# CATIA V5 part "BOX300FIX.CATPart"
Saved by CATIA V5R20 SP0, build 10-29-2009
Part number: BOX300FIX
Bounding box of the stored display mesh (mm): x 0 to 476, y -20 to 55, z -40 to 15
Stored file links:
  C:\Users\Utente\Desktop\IO LAVORO\3D X SITO CF\X SITO\PLASTICA\BOX\BOX300FIX.CATPart
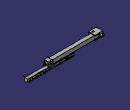
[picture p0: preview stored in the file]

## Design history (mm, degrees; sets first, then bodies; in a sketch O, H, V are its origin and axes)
Set1
  DatumSurface1 to DatumSurface16 "_ZH90/4_head"
  DatumSurface17 to DatumSurface34 "_ZH90/4_screw1"
  DatumSurface35 to DatumSurface55 "_ZH90/4_hand"
  DatumSurface56 to DatumSurface73 "_ZH90/4_screw2"
  DatumSurface74 to DatumSurface94 "_ZH90/4_he"
  DatumSurface95 to DatumSurface109 "_ZH90/4_screw3"
  DatumSurface110 to DatumSurface117 "_ZH90/4_stift1"
  DatumSurface118 to DatumSurface127 "_ZH90/4_stift2"
  DatumSurface128 to DatumSurface160 "_ZH90/05_body"
  DatumSurface161 to DatumSurface178 "_M8-5"
  DatumSurface179 to DatumSurface198 "_ST2"
  DatumSurface199 to DatumSurface213 "_ZH90/05_foot3"
  DatumSurface214 to DatumSurface230 "_M6-3"
  DatumSurface231 to DatumSurface248 "_M6-4"
  DatumSurface249 to DatumSurface260 "_ZH90/05_foot4"
  DatumSurface261 to DatumSurface280 "_ST1"
Body1 (main body)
